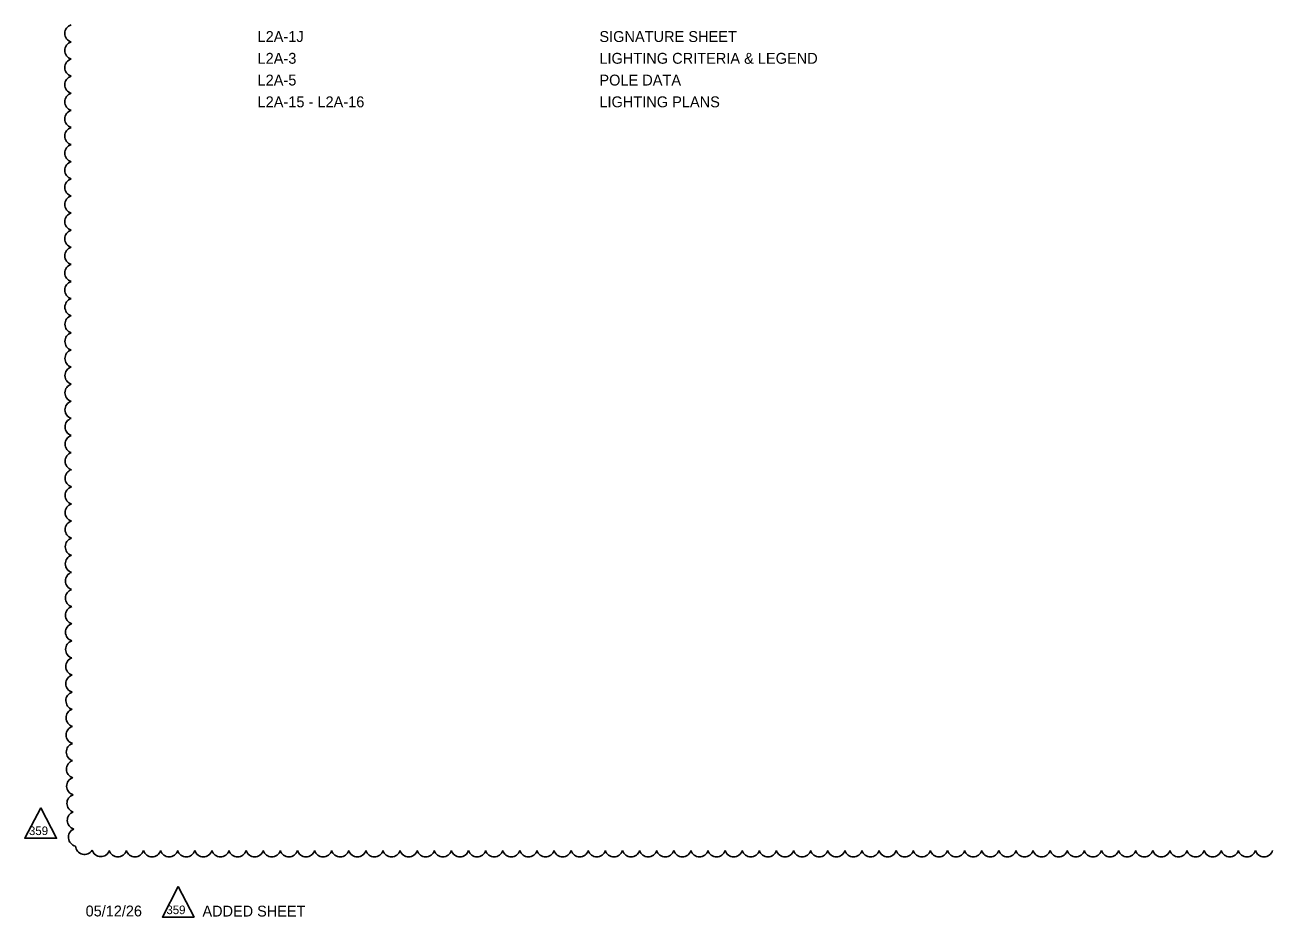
# Model space of a CAD drawing. Extents: x -811 to 10319, y -2309 to 9962.
# Drawn here: x -811.27 to -803.29, y -2308.89 to -2303.15 of the extents above; entities that cross this region are included whole.
import ezdxf

# ---------------------------------------------------------------- set-up
doc = ezdxf.new("R2010")
doc.units = 0
doc.layers.add('ScratchEle_dp', color=7, linetype='Continuous')
doc.layers.add('TextMisc', color=7, linetype='Continuous')

msp = doc.modelspace()

# ---------------------------------------------------------------- linework, layer by layer
at = {"layer": 'ScratchEle_dp'}
for points in [[(-811.1719, -2308.1812), (-811.2741, -2308.3778), (-811.0698, -2308.3778)], [(-810.2869, -2308.6886), (-810.389, -2308.8853), (-810.1848, -2308.8853)]]:
    msp.add_lwpolyline(points, close=True, dxfattribs=at)
for centre, radius, start, end in [((-810.959, -2303.2017), 0.0577, 107.5, 252.5), ((-810.959, -2303.3118), 0.0577, 107.5, 252.5), ((-810.959, -2303.4218), 0.0577, 107.5, 252.5), ((-810.959, -2303.5318), 0.0577, 107.5, 252.5), ((-810.959, -2303.6419), 0.0577, 107.5, 252.5), ((-810.959, -2303.7519), 0.0577, 107.5, 252.5), ((-810.959, -2303.862), 0.0577, 107.5, 252.5), ((-810.959, -2303.972), 0.0577, 107.5, 252.5), ((-810.959, -2304.0821), 0.0577, 107.50009, 252.50009), ((-810.959, -2304.1921), 0.0577, 107.50287, 252.50287), ((-810.959, -2304.3021), 0.0577, 107.50707, 252.50707), ((-810.9589, -2304.4122), 0.0577, 107.51144, 252.51144), ((-810.9589, -2304.5222), 0.0577, 107.51599, 252.51599), ((-810.9589, -2304.6323), 0.0577, 107.52073, 252.52073), ((-810.9588, -2304.7423), 0.0577, 107.52569, 252.52569), ((-810.9588, -2304.8524), 0.0577, 107.53088, 252.53088), ((-810.9587, -2304.9624), 0.0577, 107.53631, 252.53631), ((-810.9586, -2305.0724), 0.0577, 107.54201, 252.54201), ((-810.9585, -2305.1825), 0.0577, 107.548, 252.548), ((-810.9584, -2305.2925), 0.0577, 107.5543, 252.5543), ((-810.9583, -2305.4026), 0.0577, 107.56094, 252.56094), ((-810.9582, -2305.5126), 0.0577, 107.56795, 252.56795), ((-810.9581, -2305.6227), 0.0577, 107.57537, 252.57537), ((-810.9579, -2305.7327), 0.0577, 107.58325, 252.58325), ((-810.9578, -2305.8427), 0.0577, 107.59162, 252.59162), ((-810.9576, -2305.9528), 0.0577, 107.60055, 252.60055), ((-810.9574, -2306.0628), 0.0577, 107.61009, 252.61009), ((-810.9571, -2306.1729), 0.0577, 107.62033, 252.62033), ((-810.9569, -2306.2829), 0.0577, 107.63135, 252.63135), ((-810.9566, -2306.3929), 0.0577, 107.64325, 252.64325), ((-810.9564, -2306.503), 0.0577, 107.65616, 252.65616), ((-810.956, -2306.613), 0.0577, 107.67024, 252.67024), ((-810.9557, -2306.7231), 0.0577, 107.68566, 252.68566), ((-810.9553, -2306.8331), 0.0577, 107.70266, 252.70266), ((-810.9549, -2306.9431), 0.0577, 107.72152, 252.72152), ((-810.9545, -2307.0532), 0.0577, 107.74262, 252.74262), ((-810.954, -2307.1632), 0.0577, 107.76643, 252.76643), ((-810.9534, -2307.2732), 0.0577, 107.79359, 252.79359), ((-810.9529, -2307.3833), 0.0577, 107.82496, 252.82496), ((-810.9522, -2307.4933), 0.0577, 107.86178, 252.86178), ((-810.9515, -2307.6033), 0.0577, 107.9058, 252.9058), ((-810.9506, -2307.7134), 0.0577, 107.95976, 252.95976), ((-810.9497, -2307.8234), 0.0577, 108.02807, 253.02807), ((-810.9486, -2307.9334), 0.0577, 108.11849, 253.11849), ((-810.9473, -2308.0434), 0.0577, 108.24639, 253.24639), ((-810.9456, -2308.1533), 0.0577, 108.44819, 253.44819), ((-810.9434, -2308.2632), 0.0577, 108.8456, 253.8456), ((-810.9363, -2308.3715), 0.0577, 113.71802, 258.71802), ((-810.89, -2308.4245), 0.0576, 183.636, 328.636), ((-810.7854, -2308.4383), 0.0577, 196.27453, 341.27453), ((-810.6758, -2308.4395), 0.0577, 197.5, 342.5), ((-810.5657, -2308.4395), 0.0577, 197.5, 342.5), ((-810.4557, -2308.4395), 0.0577, 197.5, 342.5), ((-810.3457, -2308.4395), 0.0577, 197.5, 342.5), ((-810.2356, -2308.4395), 0.0577, 197.5, 342.5), ((-810.1256, -2308.4395), 0.0577, 197.5, 342.5), ((-810.0155, -2308.4395), 0.0577, 197.5, 342.5), ((-809.9055, -2308.4395), 0.0577, 197.5, 342.5), ((-809.7954, -2308.4395), 0.0577, 197.5, 342.5), ((-809.6854, -2308.4395), 0.0577, 197.5, 342.5), ((-809.5753, -2308.4395), 0.0577, 197.5, 342.5), ((-809.4653, -2308.4395), 0.0577, 197.5, 342.5), ((-809.3553, -2308.4395), 0.0577, 197.5, 342.5), ((-809.2452, -2308.4395), 0.0577, 197.5, 342.5), ((-809.1352, -2308.4395), 0.0577, 197.5, 342.5), ((-809.0251, -2308.4395), 0.0577, 197.5, 342.5), ((-808.9151, -2308.4395), 0.0577, 197.5, 342.5), ((-808.805, -2308.4395), 0.0577, 197.5, 342.5), ((-808.695, -2308.4395), 0.0577, 197.5, 342.5), ((-808.585, -2308.4395), 0.0577, 197.5, 342.5), ((-808.4749, -2308.4395), 0.0577, 197.5, 342.5), ((-808.3649, -2308.4395), 0.0577, 197.5, 342.5), ((-808.2548, -2308.4395), 0.0577, 197.5, 342.5), ((-808.1448, -2308.4395), 0.0577, 197.5, 342.5), ((-808.0347, -2308.4395), 0.0577, 197.5, 342.5), ((-807.9247, -2308.4395), 0.0577, 197.5, 342.5), ((-807.8146, -2308.4395), 0.0577, 197.5, 342.5), ((-807.7046, -2308.4395), 0.0577, 197.5, 342.5), ((-807.5946, -2308.4395), 0.0577, 197.5, 342.5), ((-807.4845, -2308.4395), 0.0577, 197.5, 342.5), ((-807.3745, -2308.4395), 0.0577, 197.5, 342.5), ((-807.2644, -2308.4395), 0.0577, 197.5, 342.5), ((-807.1544, -2308.4395), 0.0577, 197.5, 342.5), ((-807.0443, -2308.4395), 0.0577, 197.5, 342.5), ((-806.9343, -2308.4395), 0.0577, 197.5, 342.5), ((-806.8242, -2308.4395), 0.0577, 197.5, 342.5), ((-806.7142, -2308.4395), 0.0577, 197.5, 342.5), ((-806.6042, -2308.4395), 0.0577, 197.5, 342.5), ((-806.4941, -2308.4395), 0.0577, 197.5, 342.5), ((-806.3841, -2308.4395), 0.0577, 197.5, 342.5), ((-806.274, -2308.4395), 0.0577, 197.5, 342.5), ((-806.164, -2308.4395), 0.0577, 197.5, 342.5), ((-806.0539, -2308.4395), 0.0577, 197.5, 342.5), ((-805.9439, -2308.4395), 0.0577, 197.5, 342.5), ((-805.8339, -2308.4395), 0.0577, 197.5, 342.5), ((-805.7238, -2308.4395), 0.0577, 197.5, 342.5), ((-805.6138, -2308.4395), 0.0577, 197.5, 342.5), ((-805.5037, -2308.4395), 0.0577, 197.5, 342.5), ((-805.3937, -2308.4395), 0.0577, 197.5, 342.5), ((-805.2836, -2308.4395), 0.0577, 197.5, 342.5), ((-805.1736, -2308.4395), 0.0577, 197.5, 342.5), ((-805.0635, -2308.4395), 0.0577, 197.5, 342.5), ((-804.9535, -2308.4395), 0.0577, 197.5, 342.5), ((-804.8435, -2308.4395), 0.0577, 197.5, 342.5), ((-804.7334, -2308.4395), 0.0577, 197.5, 342.5), ((-804.6234, -2308.4395), 0.0577, 197.5, 342.5), ((-804.5133, -2308.4395), 0.0577, 197.5, 342.5), ((-804.4033, -2308.4395), 0.0577, 197.5, 342.5), ((-804.2932, -2308.4395), 0.0577, 197.5, 342.5), ((-804.1832, -2308.4395), 0.0577, 197.5, 342.5), ((-804.0732, -2308.4395), 0.0577, 197.5, 342.5), ((-803.9631, -2308.4395), 0.0577, 197.5, 342.5), ((-803.8531, -2308.4395), 0.0577, 197.5, 342.5), ((-803.743, -2308.4395), 0.0577, 197.5, 342.5), ((-803.633, -2308.4395), 0.0577, 197.5, 342.5), ((-803.5229, -2308.4395), 0.0577, 197.5, 342.5), ((-803.4129, -2308.4395), 0.0577, 197.5, 342.5), ((-803.3028, -2308.4395), 0.0577, 197.5, 342.5)]:
    msp.add_arc(centre, radius, start, end, dxfattribs=at)

# ---------------------------------------------------------------- texts
for s, height, p in [('359', 0.0551, (-811.2474, -2308.3573)), ('05/12/26', 0.0696, (-810.8829, -2308.8805)), ('359', 0.0551, (-810.3635, -2308.8658)), ('ADDED SHEET', 0.0696, (-810.1313, -2308.8812))]:
    msp.add_text(s, height=height, dxfattribs=at).set_placement(p)
at = {"layer": 'TextMisc'}
for s, p in [('L2A-1J', (-809.777, -2303.257)), ('SIGNATURE SHEET', (-807.5781, -2303.257)), ('L2A-3', (-809.777, -2303.397)), ('LIGHTING CRITERIA & LEGEND', (-807.5781, -2303.397)), ('L2A-5', (-809.777, -2303.537)), ('POLE DATA', (-807.5781, -2303.537)), ('L2A-15 - L2A-16', (-809.777, -2303.677)), ('LIGHTING PLANS', (-807.5781, -2303.677))]:
    msp.add_text(s, height=0.07, dxfattribs=at).set_placement(p)

doc.saveas('drawing.dxf')
